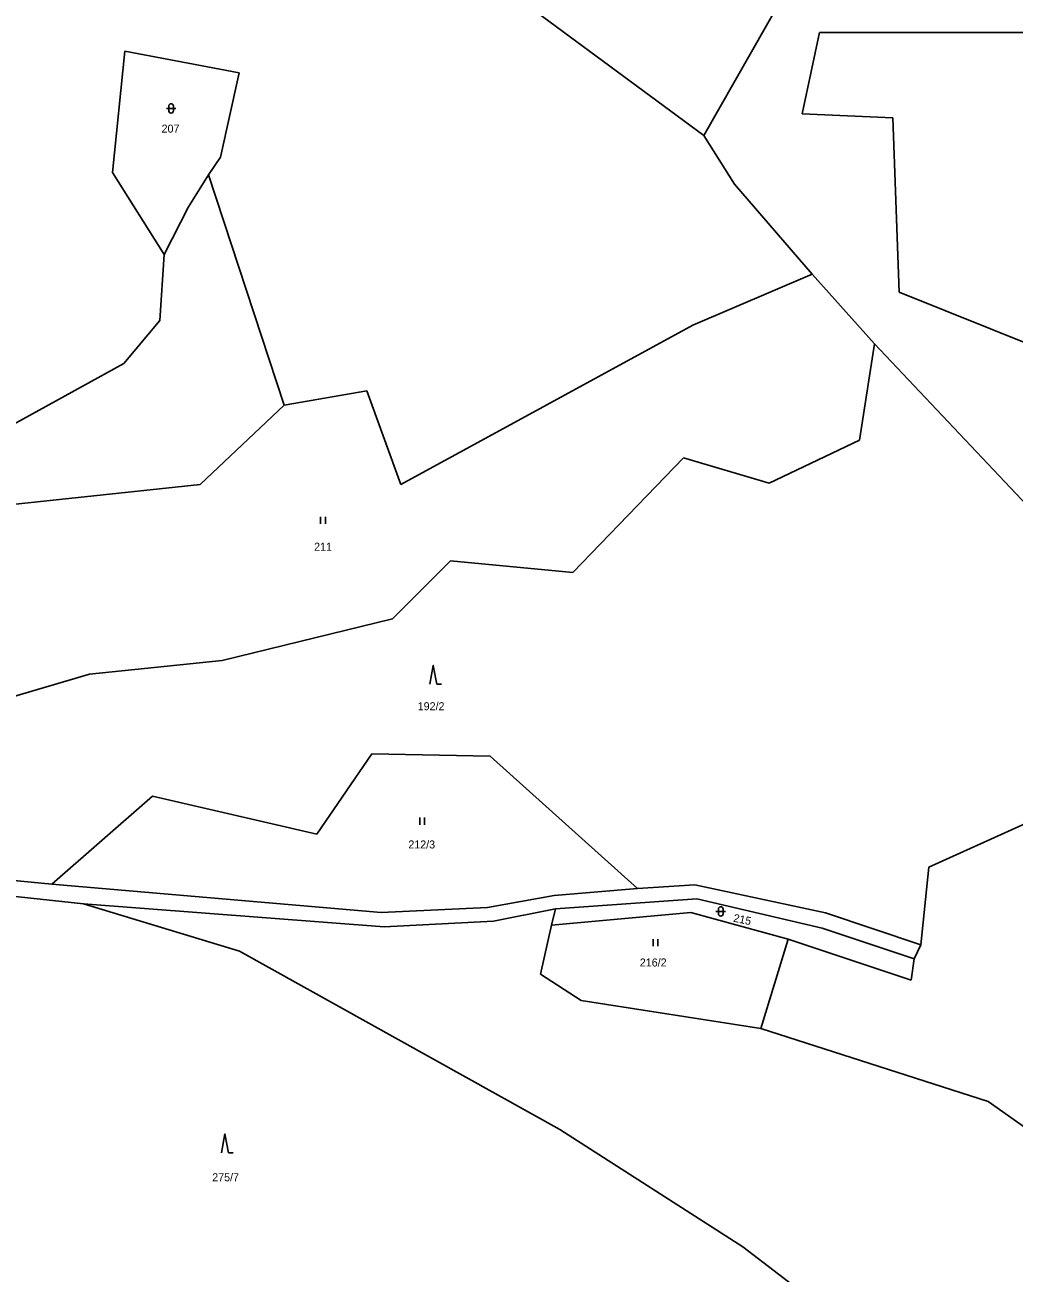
# Model space of a CAD drawing. Extents: x -754970 to -752637, y -970569 to -968179.
# Drawn here: x -753382.7 to -753172.7, y -968708.9 to -968443.9 of the extents above; entities that cross this region are included whole.
import ezdxf
from ezdxf.enums import TextEntityAlignment as Align

# ---------------------------------------------------------------- set-up
doc = ezdxf.new("R2010")
doc.units = 0
doc.header["$LTSCALE"] = 0.68
doc.layers.add('1', color=7, linetype='Continuous', lineweight=25)
doc.layers.add('3', color=7, linetype='Continuous', lineweight=25)
doc.layers.add('2', color=7, linetype='Continuous')

msp = doc.modelspace()

# ---------------------------------------------------------------- linework, layer by layer
at = {"layer": '1'}
for p, q in [((-753238.6, -968467.36), (-753286.08, -968432.31)), ((-753238.6, -968467.36), (-753218.28, -968431.73)), ((-753217.75, -968462.82), (-753214.04, -968445.55)), ((-753214.04, -968445.55), (-753168.07, -968445.55)), ((-753364.13, -968475.27), (-753361.57, -968449.49)), ((-753361.57, -968449.49), (-753337.25, -968454.09)), ((-753337.25, -968454.09), (-753341.23, -968472.02)), ((-753198.48, -968463.65), (-753217.75, -968462.82)), ((-753197.14, -968500.63), (-753198.48, -968463.65)), ((-753232.09, -968477.7), (-753238.6, -968467.36)), ((-753341.23, -968472.02), (-753343.75, -968475.75)), ((-753353.19, -968492.62), (-753364.13, -968475.27)), ((-753343.75, -968475.75), (-753347.99, -968482.54)), ((-753343.75, -968475.75), (-753327.7, -968524.63)), ((-753215.63, -968496.8), (-753232.09, -968477.7)), ((-753347.99, -968482.54), (-753353.19, -968492.62)), ((-753353.19, -968492.62), (-753354.08, -968506.65)), ((-753215.63, -968496.8), (-753240.95, -968507.69)), ((-753202.34, -968511.61), (-753215.63, -968496.8)), ((-753168.04, -968512.36), (-753197.14, -968500.63)), ((-753354.08, -968506.65), (-753361.76, -968515.77)), ((-753240.95, -968507.69), (-753302.96, -968541.47)), ((-753205.52, -968532.09), (-753202.34, -968511.61)), ((-753167.47, -968548.56), (-753202.34, -968511.61)), ((-753361.76, -968515.77), (-753420.95, -968548.45)), ((-753327.7, -968524.63), (-753310.13, -968521.58)), ((-753310.13, -968521.58), (-753302.96, -968541.47)), ((-753327.7, -968524.63), (-753345.55, -968541.51)), ((-753224.76, -968541.23), (-753205.52, -968532.09)), ((-753266.41, -968560.19), (-753242.89, -968535.83)), ((-753242.89, -968535.83), (-753224.76, -968541.23)), ((-753345.55, -968541.51), (-753389.69, -968546.22)), ((-753304.73, -968570.02), (-753292.42, -968557.71)), ((-753292.42, -968557.71), (-753266.41, -968560.19)), ((-753340.85, -968578.88), (-753304.73, -968570.02)), ((-753369.07, -968581.79), (-753340.85, -968578.88)), ((-753400.71, -968591.1), (-753369.07, -968581.79)), ((-753320.74, -968615.76), (-753309.11, -968598.67)), ((-753309.11, -968598.67), (-753283.94, -968599.19)), ((-753252.7, -968627.29), (-753283.94, -968599.19)), ((-753377.04, -968626.35), (-753355.66, -968607.69)), ((-753355.66, -968607.69), (-753320.74, -968615.76)), ((-753190.83, -968622.74), (-753166.46, -968611.71)), ((-753377.04, -968626.35), (-753415.1, -968622.69)), ((-753192.53, -968639.24), (-753190.83, -968622.74)), ((-753416.14, -968625.63), (-753370.29, -968630.52)), ((-753307.09, -968632.34), (-753377.04, -968626.35)), ((-753240.48, -968626.53), (-753252.7, -968627.29)), ((-753212.76, -968632.43), (-753240.48, -968626.53)), ((-753270.37, -968628.75), (-753284.53, -968631.34)), ((-753252.7, -968627.29), (-753270.37, -968628.75)), ((-753270.11, -968631.59), (-753240.07, -968629.47)), ((-753240.07, -968629.47), (-753213.49, -968635.67)), ((-753370.29, -968630.52), (-753337.17, -968640.58)), ((-753370.29, -968630.52), (-753306.47, -968635.39)), ((-753284.53, -968631.34), (-753307.09, -968632.34)), ((-753270.11, -968631.59), (-753283.25, -968634.19)), ((-753270.11, -968631.59), (-753270.94, -968635.05)), ((-753270.94, -968635.05), (-753241.33, -968632.36)), ((-753220.66, -968638.01), (-753241.33, -968632.36)), ((-753192.53, -968639.24), (-753212.76, -968632.43)), ((-753306.47, -968635.39), (-753283.25, -968634.19)), ((-753270.94, -968635.05), (-753273.25, -968645.44)), ((-753193.97, -968642.23), (-753213.49, -968635.67)), ((-753220.66, -968638.01), (-753226.5, -968656.97)), ((-753194.59, -968646.71), (-753220.66, -968638.01)), ((-753193.97, -968642.23), (-753192.53, -968639.24)), ((-753337.17, -968640.58), (-753269.17, -968678.43)), ((-753193.97, -968642.23), (-753194.59, -968646.71)), ((-753273.25, -968645.44), (-753264.61, -968651.03)), ((-753264.61, -968651.03), (-753226.5, -968656.97)), ((-753226.5, -968656.97), (-753178.2, -968672.53)), ((-753178.2, -968672.53), (-753154.11, -968689.64)), ((-753269.17, -968678.43), (-753230.32, -968703.37)), ((-753230.32, -968703.37), (-753190.33, -968733.98))]:
    msp.add_line(p, q, dxfattribs=at)
at = {"layer": '3'}
for p, q in [((-753352.711, -968461.631), (-753350.709, -968461.631)), ((-753352.211, -968461.131), (-753352.211, -968462.132)), ((-753351.209, -968462.132), (-753351.209, -968461.131)), ((-753319.961, -968549.87), (-753319.961, -968548.37)), ((-753318.96, -968549.87), (-753318.96, -968548.37)), ((-753295.3, -968583.9), (-753294.304, -968583.9)), ((-753298.921, -968613.73), (-753298.921, -968612.23)), ((-753297.92, -968613.73), (-753297.92, -968612.23)), ((-753236.021, -968632.151), (-753234.019, -968632.151)), ((-753235.521, -968631.651), (-753235.521, -968632.652)), ((-753234.519, -968632.652), (-753234.519, -968631.651)), ((-753249.341, -968639.53), (-753249.341, -968638.03)), ((-753248.34, -968639.53), (-753248.34, -968638.03)), ((-753339.54, -968683.38), (-753338.544, -968683.38))]:
    msp.add_line(p, q, dxfattribs=at)
for points in [[(-753295.3, -968583.9), (-753296.05, -968579.9), (-753296.8, -968583.9)], [(-753339.54, -968683.38), (-753340.29, -968679.38), (-753341.04, -968683.38)]]:
    msp.add_lwpolyline(points, dxfattribs=at)
for centre, start, end in [((-753351.71, -968461.1309), 0, 180), ((-753351.71, -968462.1309), 180, 359.98789), ((-753235.02, -968631.6509), 0, 180), ((-753235.02, -968632.6509), 180, 359.98789)]:
    msp.add_arc(centre, 0.5, start, end, dxfattribs=at)

# ---------------------------------------------------------------- texts
at = {"layer": '2'}
for s, p in [('207', (-753351.839, -968466.775)), ('211', (-753319.449, -968555.555)), ('192/2', (-753296.51, -968589.425)), ('212/3', (-753298.5, -968618.775)), ('216/2', (-753249.35, -968643.835)), ('275/7', (-753340.14, -968689.445))]:
    msp.add_text(s, height=1.7, dxfattribs=at).set_placement(p, align=Align.CENTER)
msp.add_text('215', height=1.7, rotation=348, dxfattribs=at).set_placement((-753230.5872, -968634.6943), align=Align.CENTER)

doc.saveas('drawing.dxf')
